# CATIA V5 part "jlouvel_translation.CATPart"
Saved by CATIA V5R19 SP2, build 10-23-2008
Part number: Pièce 2_coulisse
Bounding box of the stored display mesh (mm): x 0 to 200, y -5 to 5, z -5 to 25
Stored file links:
  E:\IAO_2010\iao\IAO_MMS_Groupe2\IAO_MMS_Groupe2\OK\jlouvel\jlouvel_iao\pièces cao catia ifma\jlouvel_translation.CATPart
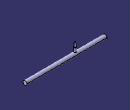
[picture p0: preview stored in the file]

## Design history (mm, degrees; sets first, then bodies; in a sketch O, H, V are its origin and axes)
Body1 (main body)
  Sketch1 on yz-plane, origin (0, 0, 0), H (0, 1, 0), V (0, 0, 1)
    circle A1 centre (0, 0) radius 5
    radius A1 = 5
  Pad1: profile Sketch1, direction (1, 0, 0), length 200
  Plane1: type Offset, RefPlane xy-plane, Offset 5
  Sketch2 on Plane1, origin (0, 0, 5), H (1, 0, 0), V (0, 1, 0)
    circle A1 centre (75, 0) radius 2
    point P1 (75, 0)
    radius A1 = 2
    distance P1 V = 75
    coincidence: P1 H
  Pad2: profile Sketch2, direction (0, 0, 1), length 20
  Sketch3 on Plane1, origin (0, 0, 5), H (1, 0, 0), V (0, 1, 0)
    circle A1 centre (75, 0) radius 3
    reference projected circle E1 centre (75, 0) radius 2 from edge [face of Pad2 from Sketch2.A1 | end face of Pad2]
    radius A1 = 3
    concentricity: A1 E1
  Pad3: profile Sketch3, direction (0, 0, -1), length 2, opposite side length 10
